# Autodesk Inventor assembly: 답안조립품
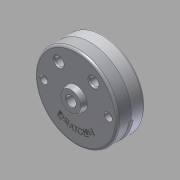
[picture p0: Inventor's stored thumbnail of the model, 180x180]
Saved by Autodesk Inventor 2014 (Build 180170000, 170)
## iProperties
Created: 2015-06
Part Number: 답안조립품
Document SubType Name: Assembly
Designer: MYHOME
Author: MYHOME
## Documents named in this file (3)
- C:\Documents and Settings\MYHOME\바탕 화면\450631V1041\답안조립품.iam
- C:\Documents and Settings\MYHOME\바탕 화면\450631V1041\본체.ipt
- C:\Documents and Settings\MYHOME\바탕 화면\450631V1041\덮개.ipt
